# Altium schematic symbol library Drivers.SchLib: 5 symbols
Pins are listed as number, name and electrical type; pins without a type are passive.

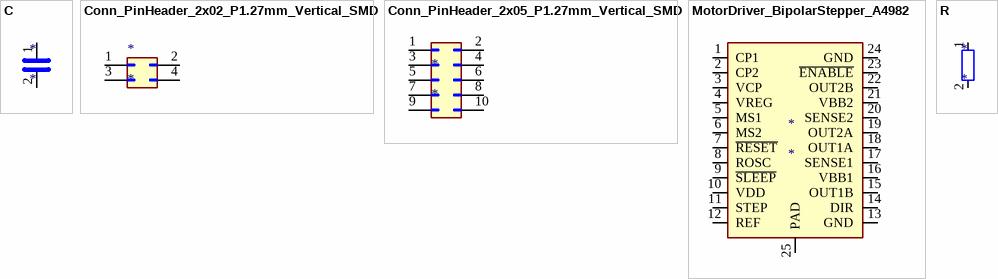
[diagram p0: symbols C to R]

## C
designator *
pins: 1, 2

## Conn_PinHeader_2x02_P1.27mm_Vertical_SMD
designator *
pins: 1 Pin_1, 2 Pin_2, 3 Pin_3, 4 Pin_4

## Conn_PinHeader_2x05_P1.27mm_Vertical_SMD
designator *
pins: 1 Pin_1, 2 Pin_2, 3 Pin_3, 4 Pin_4, 5 Pin_5, 6 Pin_6, 7 Pin_7, 8 Pin_8, 9 Pin_9, 10 Pin_10

## MotorDriver_BipolarStepper_A4982
designator *
pins: 1 CP1, 2 CP2, 3 VCP, 4 VREG, 5 MS1, 6 MS2, 7 ~{RESET}, 8 ROSC, 9 ~{SLEEP}, 10 VDD, 11 STEP, 12 REF, 13 GND, 14 DIR, 15 OUT1B, 16 VBB1, 17 SENSE1, 18 OUT1A, 19 OUT2A, 20 SENSE2, 21 VBB2, 22 OUT2B, 23 ~{ENABLE}, 24 GND, 25 PAD

## R
designator *
pins: 1, 2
